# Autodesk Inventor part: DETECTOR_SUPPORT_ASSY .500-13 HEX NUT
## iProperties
Shininess: 64.0
Length Units: 11272
Angle Units: 11279
Time Units: 11290
Mass Units: 11286
Length Display Precision: 3
Angle Display Precision: 2
Compacted: True
Part Number: DETECTOR_SUPPORT_ASSY .500-13 HEX NUT
Document SubType Name: Modeling
Created: 2004-08
Designer: John Blackburn
Material: MILD_STEEL
Manufacturer: Standard
Standards Organization: Custom
Density: 0.0
Volumn: 0.0
Area: 0.0
PropertySet Name: Model Information
Control State: 0
Master: False
Checked Out: False
Author: John Blackburn
